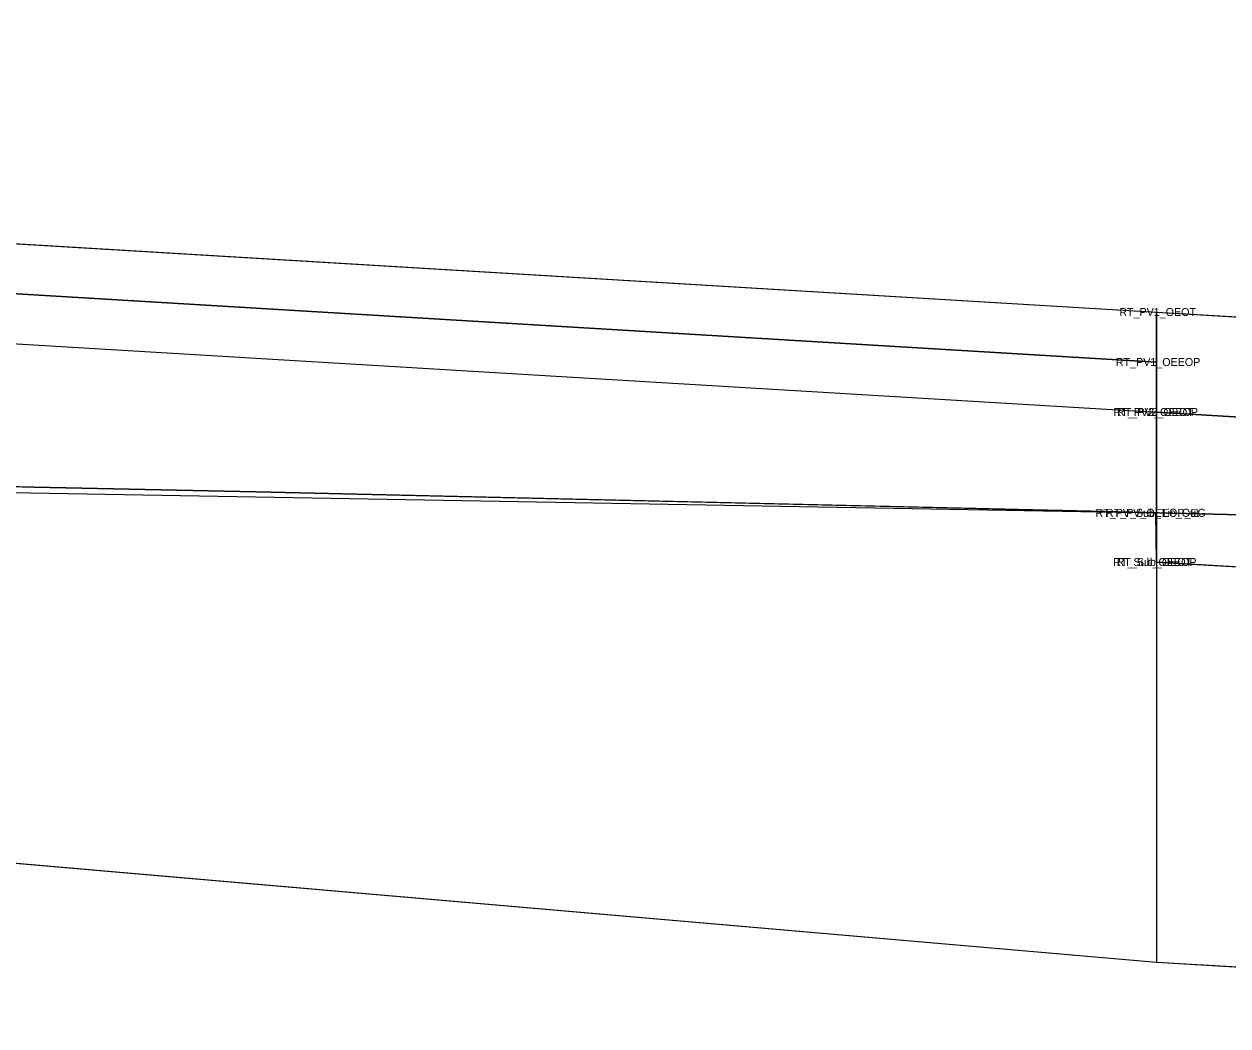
# Model space of a CAD drawing. Extents: x -516 to 303, y -10 to 5017.
# Drawn here: x 159.17 to 162.178, y 2504.204 to 2506.709 of the extents above; entities that cross this region are included whole.
import ezdxf

# ---------------------------------------------------------------- set-up
doc = ezdxf.new("R2010")
doc.units = 0
for name, color, linetype in [('Exist CMT Pavement', 7, 'Continuous'), ('Exist XS Ground Line', 7, 'Continuous'), ('Prop CMT Pvmt Course 1', 7, 'Continuous'), ('Prop CMT Pvmt Course 1 Wedge', 7, 'Continuous'), ('Prop CMT Pvmt Course 2', 7, 'Continuous'), ('Prop CMT Pvmt Course 2 Wedge', 7, 'Continuous'), ('Prop CMT Pvmt Course 3', 7, 'Continuous'), ('Prop CMT Pvmt Course 3 Wedge', 7, 'Continuous'), ('Prop CMT Pvmt Surface', 7, 'Continuous'), ('Prop CMT Pvmt Surface Shoulder', 7, 'Continuous'), ('Prop CMT Pvmt Wedge Surface 1', 7, 'Continuous'), ('Prop CMT Pvmt Wedge Surface 2', 7, 'Continuous'), ('Prop CMT Pvmt Wedge Surface 3', 7, 'Continuous'), ('Prop CMT Shld Paved Course 1', 7, 'Continuous'), ('Prop CMT Shld Paved Course 2', 7, 'Continuous'), ('Prop CMT Shld Paved Course 3', 7, 'Continuous'), ('Prop CMT Subgrade Earthwork', 7, 'Continuous'), ('Prop Road Sect_ Misc - Drafting Aid (solid line)', 7, 'Continuous'), ('Prop Road Sect_ Recs - UC Shallow (Outline)', 7, 'Continuous'), ('Prop Road Sect_ Recs - UC Shallow (Pattern)', 7, 'Continuous'), ('Scratch_Level_0', 7, 'Continuous')]:
    doc.layers.add(name, color=color, linetype=linetype)

msp = doc.modelspace()

# ---------------------------------------------------------------- linework, layer by layer
at = {"layer": 'Exist CMT Pavement'}
msp.add_lwpolyline([(150.0015, 2505.7005), (161.9985, 2505.4873)], dxfattribs=at)
at = {"layer": 'Exist XS Ground Line'}
msp.add_lwpolyline([(131.6756, 2506.039), (149.0951, 2505.7181), (150.1702, 2505.6981), (151.2449, 2505.6798), (153.9281, 2505.658), (155.8468, 2505.6298), (156.5413, 2505.6134), (157.7961, 2505.5833), (159.1952, 2505.5519), (159.7504, 2505.5399), (161.3095, 2505.5036), (161.8359, 2505.4913), (163.6405, 2505.4476), (164.4857, 2505.426), (165.5232, 2505.4046), (166.0583, 2505.3912), (166.8223, 2505.373), (167.2292, 2505.3687), (168.2607, 2505.3287)], dxfattribs=at)
at = {"layer": 'Prop CMT Pvmt Course 1'}
for points in [[(150, 2506.7094), (162, 2505.9894)], [(162, 2505.8644), (150, 2506.5844)], [(162, 2505.9894), (162, 2505.7394), (162, 2505.7393), (162, 2505.8644)]]:
    msp.add_lwpolyline(points, dxfattribs=at)
at = {"layer": 'Prop CMT Pvmt Course 1 Wedge'}
msp.add_lwpolyline([(150, 2506.5844), (162, 2505.8644)], dxfattribs=at)
at = {"layer": 'Prop CMT Pvmt Course 2'}
msp.add_lwpolyline([(162, 2505.7394), (162, 2505.7393), (162, 2505.7393)], close=True, dxfattribs=at)
msp.add_lwpolyline([(162, 2505.7394), (162, 2505.7394)], dxfattribs=at)
at = {"layer": 'Prop CMT Pvmt Course 2 Wedge'}
msp.add_lwpolyline([(150, 2506.4593), (162, 2505.7393)], dxfattribs=at)
at = {"layer": 'Prop CMT Pvmt Course 3'}
for points in [[(162, 2505.7393), (162, 2505.7394), (162, 2505.3644), (162, 2505.3643)], [(162, 2505.3643), (162, 2505.7393)]]:
    msp.add_lwpolyline(points, dxfattribs=at)
at = {"layer": 'Prop CMT Pvmt Course 3 Wedge'}
msp.add_lwpolyline([(150, 2506.4593), (162, 2505.7393)], dxfattribs=at)
at = {"layer": 'Prop CMT Pvmt Surface'}
msp.add_line((150, 2506.7094), (162, 2505.9894), dxfattribs=at)
at = {"layer": 'Prop CMT Pvmt Surface Shoulder'}
msp.add_line((162, 2505.9894), (164, 2505.8694), dxfattribs=at)
at = {"layer": 'Prop CMT Pvmt Wedge Surface 1'}
for points in [[(150, 2506.5844), (162, 2505.8644)], [(162, 2505.7394), (162, 2505.9894)], [(162, 2505.8644), (162, 2505.7393), (162, 2505.7394)]]:
    msp.add_lwpolyline(points, dxfattribs=at)
at = {"layer": 'Prop CMT Pvmt Wedge Surface 2'}
for points in [[(150, 2506.4593), (162, 2505.7394)], [(162, 2505.7394), (162, 2505.9894)]]:
    msp.add_lwpolyline(points, dxfattribs=at)
at = {"layer": 'Prop CMT Pvmt Wedge Surface 3'}
for points in [[(150, 2506.4593), (162, 2505.7394)], [(162, 2505.7394), (162, 2505.9894)]]:
    msp.add_lwpolyline(points, dxfattribs=at)
at = {"layer": 'Prop CMT Shld Paved Course 1'}
for points in [[(162, 2505.9894), (164, 2505.8694), (164.266, 2505.6034)], [(162, 2505.7394), (162, 2505.9894)], [(164.266, 2505.6034), (162, 2505.7394)]]:
    msp.add_lwpolyline(points, dxfattribs=at)
at = {"layer": 'Prop CMT Shld Paved Course 2'}
for points in [[(162, 2505.7394), (164.266, 2505.6034)], [(164.266, 2505.6034), (162, 2505.7394)], [(162, 2505.7394), (162, 2505.7394)]]:
    msp.add_lwpolyline(points, dxfattribs=at)
at = {"layer": 'Prop CMT Shld Paved Course 3'}
for points in [[(162, 2505.7394), (164.266, 2505.6034)], [(162, 2505.3644), (162, 2505.7394)], [(164.6649, 2505.2045), (162, 2505.3644)]]:
    msp.add_lwpolyline(points, dxfattribs=at)
at = {"layer": 'Prop CMT Subgrade Earthwork'}
for p, q in [((162, 2505.3643), (161.9985, 2505.4873)), ((162, 2505.3644), (164.6649, 2505.2045)), ((162, 2505.3643), (162, 2505.3644))]:
    msp.add_line(p, q, dxfattribs=at)
at = {"layer": 'Prop Road Sect_ Misc - Drafting Aid (solid line)'}
for p, q in [((148, 2505.5794), (162, 2504.3643)), ((162, 2505.3643), (162, 2504.3643)), ((162, 2504.3643), (164.6649, 2504.2045))]:
    msp.add_line(p, q, dxfattribs=at)
at = {"layer": 'Prop Road Sect_ Recs - UC Shallow (Outline)'}
msp.add_lwpolyline([(165.6649, 2504.2045), (165.6649, 2505.2045), (165.6649, 2505.401), (165.5232, 2505.4046), (164.4857, 2505.426), (163.6405, 2505.4476), (161.8359, 2505.4913), (159.7504, 2505.5399), (159.1952, 2505.5519), (157.7961, 2505.5833), (156.5413, 2505.6134), (155.8468, 2505.6298), (153.9281, 2505.658), (151.2449, 2505.6798), (150, 2505.7013), (149.0951, 2505.7181), (148.0015, 2505.7383), (148, 2505.5794), (162, 2504.3643), (164.6649, 2504.2045)], close=True, dxfattribs=at)
at = {"layer": 'Prop Road Sect_ Recs - UC Shallow (Pattern)'}
msp.add_lwpolyline([(165.6649, 2504.2045), (165.6649, 2505.2045), (165.6649, 2505.401), (165.5232, 2505.4046), (164.4857, 2505.426), (163.6405, 2505.4476), (161.8359, 2505.4913), (159.7504, 2505.5399), (159.1952, 2505.5519), (157.7961, 2505.5833), (156.5413, 2505.6134), (155.8468, 2505.6298), (153.9281, 2505.658), (151.2449, 2505.6798), (150, 2505.7013), (149.0951, 2505.7181), (148.0015, 2505.7383), (148, 2505.5794), (162, 2504.3643), (164.6649, 2504.2045), (165.6649, 2504.2045)], dxfattribs=at)

# ---------------------------------------------------------------- texts
at = {"layer": 'Scratch_Level_0'}
for s, p in [('RT_PV1_OEOT', (161.9069, 2505.9794)), ('RT_PV1_OEEOP', (161.8983, 2505.8544)), ('RT_PV2_OEEOP', (161.8926, 2505.7293)), ('RT_PV3_OEEOP', (161.8926, 2505.7293)), ('RT_PV3_OEOT', (161.9013, 2505.7294)), ('RT_PV2_OEOT', (161.9013, 2505.7294)), ('RT_PV_Sub_Tie_Out', (161.8475, 2505.4773)), ('RT_PV_OEEOP_EG', (161.8735, 2505.4773)), ('RT_Sub_OEEOP', (161.8917, 2505.3543)), ('RT_Sub_OEOT', (161.9003, 2505.3544))]:
    msp.add_text(s, height=0.02, dxfattribs=at).set_placement(p)

doc.saveas('drawing.dxf')
